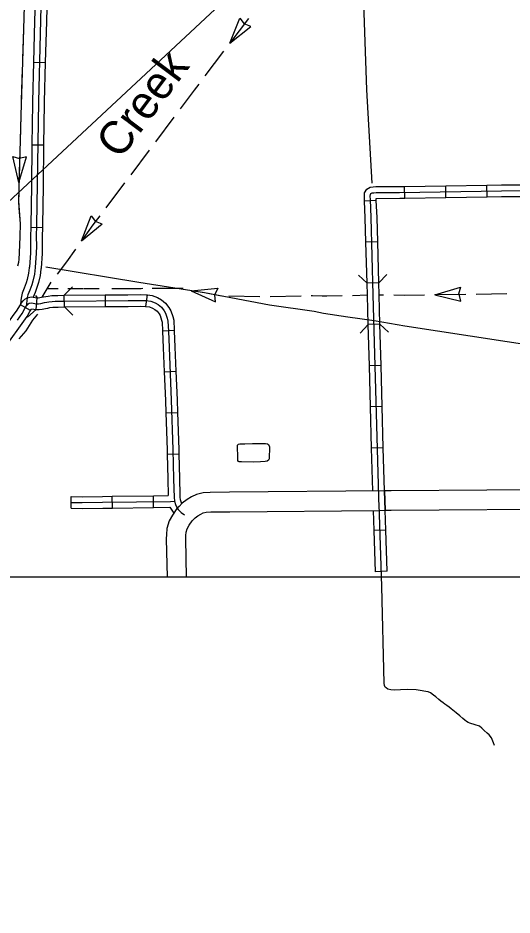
# Model space of a CAD drawing. Extents: x -5566 to 1759129, y -3726 to 731467.
# Drawn here: x -4880.9 to -4832.8, y 127.6 to 214.9 of the extents above; entities that cross this region are included whole.
import ezdxf

# ---------------------------------------------------------------- set-up
doc = ezdxf.new("R2010")
doc.units = 0
doc.layers.add('Default', color=7, linetype='Continuous')
doc.layers.add('R_No Plot', color=7, linetype='Continuous')

msp = doc.modelspace()

# ---------------------------------------------------------------- linework, layer by layer
at = {"layer": 'Default'}
for p, q in [((-4860.295, 212.486), (-4859.315, 214.901)), ((-4859.315, 214.901), (-4858.888, 214.354)), ((-4860.295, 212.486), (-4858.239, 214.087)), ((-4858.239, 214.087), (-4858.881, 214.348)), ((-4879.395, 210.612), (-4878.256, 210.583)), ((-4879.554, 202.588), (-4878.415, 202.571)), ((-4880.818, 198.922), (-4881.426, 201.457)), ((-4881.426, 201.457), (-4880.76, 201.26)), ((-4880.818, 198.922), (-4880.077, 201.421)), ((-4880.077, 201.421), (-4880.751, 201.259)), ((-4843.264, 197.397), (-4843.282, 198.536)), ((-4839.255, 197.462), (-4839.273, 198.601)), ((-4835.245, 197.528), (-4835.264, 198.667)), ((-4846.032, 197.166), (-4847.17, 197.114)), ((-4874.734, 193.243), (-4873.801, 195.676)), ((-4873.786, 195.679), (-4873.358, 195.133)), ((-4874.734, 193.243), (-4872.709, 194.883)), ((-4872.707, 194.869), (-4873.351, 195.128)), ((-4879.675, 194.576), (-4878.536, 194.546)), ((-4845.893, 193.148), (-4847.032, 193.118)), ((-4864.05, 188.384), (-4861.457, 188.641)), ((-4861.457, 188.641), (-4861.743, 188.008)), ((-4845.785, 189.14), (-4846.924, 189.109)), ((-4840.325, 187.978), (-4837.829, 188.726)), ((-4837.829, 188.726), (-4838.013, 188.057)), ((-4879.128, 186.558), (-4879.031, 187.693)), ((-4876.388, 186.809), (-4876.415, 187.948)), ((-4872.387, 186.841), (-4872.396, 187.98)), ((-4868.456, 186.853), (-4868.31, 187.982)), ((-4864.05, 188.384), (-4861.676, 187.309)), ((-4861.676, 187.309), (-4861.744, 188)), ((-4840.325, 187.978), (-4837.789, 187.378)), ((-4837.789, 187.378), (-4837.964, 188.049)), ((-4879.685, 186.478), (-4880.681, 187.031)), ((-4845.676, 185.132), (-4846.815, 185.101)), ((-4866.835, 184.501), (-4865.697, 184.565)), ((-4845.566, 181.124), (-4846.705, 181.092)), ((-4866.675, 180.504), (-4865.537, 180.549)), ((-4866.523, 176.501), (-4865.385, 176.539)), ((-4845.457, 177.115), (-4846.595, 177.084)), ((-4845.347, 173.107), (-4846.486, 173.076)), ((-4866.393, 172.496), (-4865.254, 172.528)), ((-4875.743, 167.219), (-4875.734, 168.358)), ((-4871.721, 167.246), (-4871.737, 168.385)), ((-4867.712, 167.302), (-4867.728, 168.441)), ((-4845.092, 165.095), (-4846.231, 165.059)), ((-4844.966, 161.087), (-4846.104, 161.051))]:
    msp.add_line(p, q, dxfattribs=at)
for points in [[(-4956.368, 127.644), (-4956.368, 127.644), (-4810.331, 263.678)], [(-4878.166, 244.422), (-4879.997, 227.523), (-4880.39, 213.843), (-4880.646, 205.424), (-4880.866, 197.098), (-4880.707, 194.91), (-4880.743, 193.671), (-4880.796, 192.074), (-4880.84, 191.464), (-4880.862, 191.122), (-4880.949, 190.772)], [(-4846.424, 198.867), (-4846.934, 207.924), (-4847.618, 227.578)], [(-4878.417, 226.631), (-4878.923, 206.778), (-4879.1, 194.766), (-4879.13, 193.666), (-4879.121, 192.719), (-4879.136, 192.031), (-4879.233, 190.653), (-4879.32, 189.984), (-4879.47, 189.321), (-4879.575, 188.977), (-4879.773, 188.435), (-4879.954, 187.984), (-4880.026, 187.722), (-4880.062, 187.415), (-4880.107, 186.891)], [(-4879.191, 218.629), (-4879.293, 214.62)], [(-4878.052, 218.6), (-4878.154, 214.591)], [(-4858.481, 214.885), (-4860.295, 212.486)], [(-4880.387, 213.953), (-4880.39, 213.843), (-4880.478, 210.947)], [(-4879.293, 214.62), (-4879.395, 210.612)], [(-4878.154, 214.591), (-4878.256, 210.583)], [(-4860.9, 211.687), (-4861.807, 210.488)], [(-4879.395, 210.612), (-4879.492, 206.789), (-4879.495, 206.597)], [(-4878.256, 210.583), (-4878.353, 206.766), (-4878.356, 206.58)], [(-4861.807, 210.488), (-4862.714, 209.289)], [(-4880.509, 209.945), (-4880.6, 206.939)], [(-4863.319, 208.489), (-4863.752, 207.916), (-4865.127, 206.086)], [(-4879.495, 206.597), (-4879.554, 202.588)], [(-4878.356, 206.58), (-4878.415, 202.571)], [(-4880.63, 205.937), (-4880.646, 205.424), (-4880.712, 202.931)], [(-4865.729, 205.284), (-4867.535, 202.88)], [(-4879.554, 202.588), (-4879.613, 198.579)], [(-4878.415, 202.571), (-4878.474, 198.562)], [(-4880.738, 201.929), (-4880.818, 198.922)], [(-4868.137, 202.078), (-4869.943, 199.673)], [(-4879.613, 198.579), (-4879.67, 194.778), (-4879.675, 194.576)], [(-4878.474, 198.562), (-4878.531, 194.754), (-4878.536, 194.546)], [(-4870.545, 198.872), (-4872.351, 196.467)], [(-4847.17, 197.114), (-4847.177, 197.255), (-4847.185, 197.594), (-4847.169, 197.9), (-4846.964, 198.258), (-4846.608, 198.459), (-4846.316, 198.492), (-4846.059, 198.513), (-4843.762, 198.528), (-4843.282, 198.536)], [(-4846.324, 187.972), (-4846.526, 195.499), (-4846.607, 197.275), (-4846.615, 197.587), (-4846.607, 197.735), (-4846.548, 197.839), (-4846.429, 197.906), (-4846.261, 197.925), (-4846.033, 197.944), (-4843.755, 197.958), (-4833.845, 198.12), (-4826.775, 198.14), (-4822.075, 198.177), (-4808.11, 198.424)], [(-4843.282, 198.536), (-4839.273, 198.601)], [(-4839.273, 198.601), (-4835.264, 198.667)], [(-4835.264, 198.667), (-4833.851, 198.69), (-4831.247, 198.697)], [(-4880.844, 197.92), (-4880.866, 197.098), (-4880.817, 196.419)], [(-4846.032, 197.166), (-4846.038, 197.294), (-4846.04, 197.372), (-4846.008, 197.375), (-4843.749, 197.389), (-4843.264, 197.397)], [(-4843.264, 197.397), (-4839.255, 197.462)], [(-4839.255, 197.462), (-4835.245, 197.528)], [(-4835.245, 197.528), (-4833.84, 197.551), (-4831.244, 197.558)], [(-4880.817, 196.419), (-4880.707, 194.919)], [(-4847.032, 193.118), (-4847.095, 195.478), (-4847.17, 197.114)], [(-4845.893, 193.148), (-4845.956, 195.52), (-4846.032, 197.166)], [(-4872.953, 195.666), (-4873.614, 194.785), (-4874.734, 193.243)], [(-4880.736, 193.917), (-4880.743, 193.671), (-4880.796, 192.074), (-4880.84, 191.464), (-4880.862, 191.122), (-4880.913, 190.919)], [(-4879.675, 194.576), (-4879.7, 193.671), (-4879.691, 192.722), (-4879.705, 192.057), (-4879.8, 190.71), (-4879.811, 190.629)], [(-4878.536, 194.546), (-4878.56, 193.661), (-4878.551, 192.715), (-4878.567, 192.005), (-4878.666, 190.596), (-4878.681, 190.483)], [(-4846.924, 189.109), (-4847.032, 193.118)], [(-4845.785, 189.14), (-4845.893, 193.148)], [(-4875.323, 192.431), (-4876.206, 191.215)], [(-4876.206, 191.215), (-4877.09, 189.998)], [(-4879.811, 190.629), (-4879.882, 190.084), (-4880.021, 189.467), (-4880.115, 189.158), (-4880.305, 188.639), (-4880.495, 188.166), (-4880.587, 187.831), (-4880.629, 187.473), (-4880.681, 187.031)], [(-4878.681, 190.483), (-4878.759, 189.885), (-4878.919, 189.175), (-4879.035, 188.796), (-4879.242, 188.231), (-4879.433, 187.754)], [(-4826.935, 182.452), (-4843.256, 184.94), (-4846.227, 185.456), (-4848.789, 185.805), (-4851.152, 186.181), (-4852.083, 186.359), (-4856.427, 186.982), (-4862.755, 188.176), (-4869.158, 189.202), (-4878.205, 190.691)], [(-4846.924, 189.109), (-4847.751, 189.893)], [(-4845.002, 189.967), (-4845.785, 189.14)], [(-4877.713, 189.213), (-4877.717, 189.208), (-4878.6, 187.759)], [(-4877.005, 188.573), (-4878.105, 188.571)], [(-4876.41, 187.948), (-4875.618, 188.766)], [(-4874.573, 188.578), (-4876.076, 188.575)], [(-4872.995, 188.581), (-4874.499, 188.578)], [(-4868.764, 188.589), (-4868.924, 188.588), (-4871.771, 188.583)], [(-4864.828, 188.614), (-4867.835, 188.595)], [(-4846.815, 185.101), (-4846.893, 187.956), (-4846.924, 189.109)], [(-4845.676, 185.132), (-4845.754, 187.987), (-4845.785, 189.14)], [(-4880.681, 187.031), (-4880.582, 187.21), (-4880.424, 187.407), (-4880.262, 187.569), (-4880.025, 187.712), (-4879.64, 187.785), (-4879.031, 187.693), (-4878.948, 187.689), (-4878.793, 187.719), (-4878.42, 187.795), (-4878.206, 187.828), (-4877.991, 187.87), (-4877.627, 187.91), (-4877.323, 187.927), (-4877.033, 187.933), (-4876.415, 187.948)], [(-4879.221, 187.918), (-4879.031, 187.693)], [(-4876.44, 187.947), (-4876.415, 187.948), (-4872.422, 187.98)], [(-4872.422, 187.98), (-4870.229, 187.997), (-4869.027, 188.014), (-4868.445, 187.996), (-4868.336, 187.982)], [(-4868.31, 187.982), (-4867.838, 187.921), (-4867.327, 187.728), (-4866.951, 187.512), (-4866.547, 187.188), (-4866.22, 186.76), (-4866.039, 186.445), (-4865.843, 185.869), (-4865.751, 185.523), (-4865.697, 184.565)], [(-4861.089, 187.862), (-4862.755, 188.176), (-4864.05, 188.384)], [(-4857.364, 187.804), (-4860.37, 187.869)], [(-4853.355, 187.862), (-4856.361, 187.794)], [(-4850.849, 187.868), (-4851.294, 187.865), (-4852.242, 187.887), (-4852.353, 187.885)], [(-4849.346, 187.878), (-4850.849, 187.868)], [(-4846.893, 187.941), (-4848.343, 187.898)], [(-4834.528, 144.15), (-4834.61, 144.406), (-4834.668, 144.575), (-4834.802, 144.883), (-4835.026, 145.173), (-4835.227, 145.349), (-4835.517, 145.593), (-4835.738, 145.838), (-4835.994, 146.007), (-4836.396, 146.158), (-4836.925, 146.321), (-4837.094, 146.379), (-4837.239, 146.461), (-4837.416, 146.605), (-4837.612, 146.776), (-4837.902, 147.015), (-4838.24, 147.31), (-4838.747, 147.721), (-4838.925, 147.857), (-4839.153, 148.02), (-4839.339, 148.147), (-4839.529, 148.285), (-4839.751, 148.465), (-4839.946, 148.628), (-4840.234, 148.882), (-4840.449, 149.053), (-4840.737, 149.266), (-4840.97, 149.353), (-4841.22, 149.411), (-4841.744, 149.502), (-4842.139, 149.551), (-4843.034, 149.586), (-4843.685, 149.563), (-4844.264, 149.535), (-4844.598, 149.542), (-4844.913, 149.627), (-4845.055, 149.743), (-4845.165, 149.822), (-4845.244, 149.993), (-4845.273, 150.197), (-4845.489, 159.621), (-4845.741, 167.608), (-4845.773, 167.97), (-4845.787, 168.364), (-4846.324, 187.972)], [(-4845.337, 187.951), (-4845.753, 187.954)], [(-4841.328, 187.964), (-4843.301, 187.937), (-4844.335, 187.944)], [(-4837.318, 188.019), (-4840.325, 187.978)], [(-4833.309, 188.074), (-4836.316, 188.033)], [(-4882.901, 183.876), (-4882.784, 183.997), (-4881.437, 185.868), (-4880.992, 186.496), (-4880.737, 186.93), (-4880.681, 187.031)], [(-4880.974, 185.537), (-4880.514, 186.187), (-4880.243, 186.647), (-4880.107, 186.891), (-4879.999, 187.027), (-4879.909, 187.117), (-4879.819, 187.171), (-4879.629, 187.207)], [(-4879.685, 186.478), (-4879.633, 186.573), (-4879.591, 186.625), (-4879.144, 186.558), (-4878.866, 186.545), (-4878.571, 186.602), (-4878.221, 186.673), (-4878.011, 186.705), (-4877.819, 186.743), (-4877.533, 186.775), (-4877.279, 186.789), (-4877.007, 186.794), (-4876.388, 186.809)], [(-4879.629, 187.207), (-4879.088, 187.126), (-4878.907, 187.117), (-4878.682, 187.161), (-4878.32, 187.234), (-4878.108, 187.267), (-4877.905, 187.306), (-4877.58, 187.343), (-4877.301, 187.358), (-4877.02, 187.364), (-4876.38, 187.379), (-4870.197, 187.428), (-4869.006, 187.445), (-4868.464, 187.428), (-4867.977, 187.365), (-4867.571, 187.211), (-4867.273, 187.04), (-4866.957, 186.787), (-4866.695, 186.444), (-4866.56, 186.209), (-4866.389, 185.704), (-4866.316, 185.433), (-4866.262, 184.467), (-4866.199, 182.86), (-4865.994, 177.742), (-4865.835, 172.929), (-4865.757, 170.101), (-4865.718, 168.232), (-4865.691, 167.989), (-4865.679, 167.92), (-4865.572, 167.601), (-4865.477, 167.357), (-4865.303, 167.096), (-4865.033, 166.818), (-4864.702, 166.595)], [(-4875.574, 186.016), (-4876.392, 186.809)], [(-4876.371, 186.809), (-4872.387, 186.841)], [(-4872.387, 186.841), (-4870.191, 186.859), (-4869.011, 186.875), (-4868.51, 186.86), (-4868.456, 186.853)], [(-4868.456, 186.853), (-4868.116, 186.809), (-4867.815, 186.695), (-4867.595, 186.568), (-4867.368, 186.386), (-4867.171, 186.128), (-4867.081, 185.973), (-4866.934, 185.539), (-4866.882, 185.343), (-4866.835, 184.501)], [(-4882.079, 183.087), (-4881.907, 183.266), (-4880.51, 185.206), (-4880.035, 185.877), (-4879.748, 186.365), (-4879.685, 186.478)], [(-4879.025, 186.104), (-4879.498, 185.529), (-4880.157, 184.49), (-4880.838, 183.713)], [(-4879.128, 186.558), (-4880, 185.824)], [(-4847.598, 184.273), (-4846.815, 185.101)], [(-4846.705, 181.092), (-4846.815, 185.101)], [(-4845.566, 181.124), (-4845.676, 185.132)], [(-4845.676, 185.132), (-4844.849, 184.349)], [(-4866.835, 184.501), (-4866.831, 184.44), (-4866.768, 182.837), (-4866.675, 180.504)], [(-4865.697, 184.565), (-4865.693, 184.494), (-4865.63, 182.882), (-4865.537, 180.549)], [(-4846.595, 177.084), (-4846.705, 181.092)], [(-4845.457, 177.115), (-4845.566, 181.124)], [(-4866.675, 180.504), (-4866.563, 177.721), (-4866.523, 176.501)], [(-4865.537, 180.549), (-4865.425, 177.763), (-4865.385, 176.539)], [(-4866.523, 176.501), (-4866.404, 172.912), (-4866.393, 172.496)], [(-4865.385, 176.539), (-4865.266, 172.947), (-4865.254, 172.528)], [(-4846.486, 173.076), (-4846.595, 177.084)], [(-4845.347, 173.107), (-4845.457, 177.115)], [(-4857.958, 171.722), (-4859.167, 171.731), (-4859.367, 171.731), (-4859.445, 171.766), (-4859.506, 171.861), (-4859.498, 172.079), (-4859.532, 173.349), (-4859.445, 173.471), (-4859.324, 173.506), (-4858.819, 173.497), (-4858.079, 173.532)], [(-4858.079, 173.532), (-4857.488, 173.532), (-4856.801, 173.524), (-4856.627, 173.497), (-4856.531, 173.436), (-4856.435, 173.193), (-4856.453, 172.027), (-4856.531, 171.905), (-4856.644, 171.8), (-4856.862, 171.783), (-4857.305, 171.748), (-4857.958, 171.722)], [(-4846.372, 168.914), (-4846.486, 173.076)], [(-4845.232, 168.921), (-4845.347, 173.107)], [(-4866.393, 172.496), (-4866.326, 170.087), (-4866.293, 168.461)], [(-4865.254, 172.528), (-4865.187, 170.115), (-4865.154, 168.515)], [(-4867.728, 168.441), (-4866.293, 168.461)], [(-4845.232, 168.921), (-4860.309, 168.787), (-4862.204, 168.77), (-4862.887, 168.731), (-4863.534, 168.56), (-4864.005, 168.338), (-4864.435, 168.087), (-4864.92, 167.726), (-4865.229, 167.41), (-4865.434, 167.206), (-4865.878, 166.567), (-4866.184, 165.985), (-4866.426, 165.263), (-4866.469, 164.674), (-4866.478, 164.245), (-4866.385, 160.507), (-4866.385, 160.507), (-4866.385, 160.507)], [(-4865.154, 168.515), (-4865.149, 168.269), (-4865.127, 168.071), (-4865.125, 168.061), (-4864.995, 167.67)], [(-4864.497, 160.507), (-4864.497, 160.507), (-4864.579, 164.246), (-4864.572, 164.583), (-4864.55, 164.887), (-4864.433, 165.236), (-4864.252, 165.579), (-4863.971, 165.984), (-4863.88, 166.075), (-4863.667, 166.292), (-4863.388, 166.5), (-4863.121, 166.655), (-4862.881, 166.768), (-4862.588, 166.846), (-4862.141, 166.872), (-4860.291, 166.889), (-4845.767, 167.021), (-4845.153, 167.023), (-4845.232, 168.921)], [(-4815.415, 167.558), (-4815.683, 167.665), (-4815.891, 167.803), (-4816.066, 167.974), (-4816.223, 168.205), (-4816.32, 168.431), (-4816.375, 168.721), (-4816.37, 168.998), (-4816.316, 169.252), (-4816.542, 169.184), (-4816.749, 169.158), (-4817.38, 169.132), (-4825.946, 169.059), (-4844.593, 168.924), (-4845.232, 168.921), (-4845.153, 167.023)], [(-4875.739, 167.789), (-4874.667, 167.779), (-4872.671, 167.803), (-4866.064, 167.895), (-4865.679, 167.92)], [(-4875.734, 168.358), (-4874.668, 168.349), (-4872.679, 168.372), (-4871.737, 168.385)], [(-4871.737, 168.385), (-4867.728, 168.441)], [(-4875.743, 167.219), (-4874.666, 167.21), (-4872.664, 167.233), (-4871.721, 167.246)], [(-4871.721, 167.246), (-4867.712, 167.302)], [(-4867.712, 167.302), (-4866.139, 167.324)], [(-4866.139, 167.324), (-4865.753, 166.746)], [(-4846.231, 165.059), (-4846.292, 167.016)], [(-4845.153, 167.023), (-4844.583, 167.025), (-4825.931, 167.161), (-4817.334, 167.234), (-4816.59, 167.264), (-4816.144, 167.321), (-4815.749, 167.44), (-4815.415, 167.558)], [(-4845.092, 165.095), (-4845.153, 167.023)], [(-4846.104, 161.051), (-4846.231, 165.059)], [(-4844.966, 161.087), (-4845.092, 165.095)]]:
    msp.add_lwpolyline(points, dxfattribs=at)
at = {"layer": 'R_No Plot'}
msp.add_lwpolyline([(-5018.988, 168.239), (-5018.988, 511.979), (-4446.603, 511.979), (-4446.603, 160.504), (-4913.433, 160.504)], dxfattribs=at)

# ---------------------------------------------------------------- texts
at = {"layer": 'Default'}
msp.add_text('Creek', height=3.2048, rotation=53.1448, dxfattribs=at).set_placement((-4870.98, 201.062))

doc.saveas('drawing.dxf')
